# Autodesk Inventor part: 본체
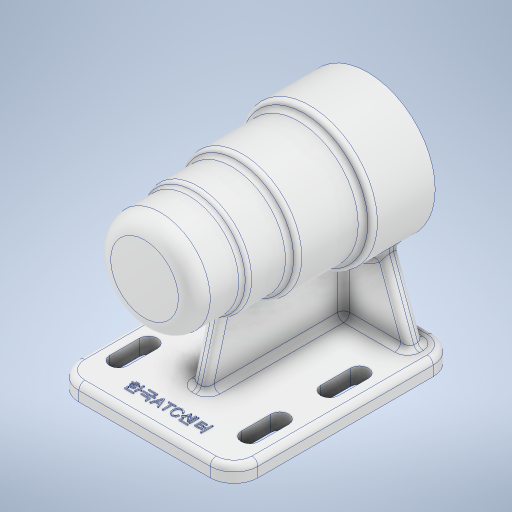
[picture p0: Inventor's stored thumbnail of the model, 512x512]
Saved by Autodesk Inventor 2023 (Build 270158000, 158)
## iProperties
Created: 2022-07
Part Number: 본체
Material: 알루미늄 6061
Document SubType Name: Modeling
Designer: owner
Density: 2.7 g/cm^3
Appearance: 알루미늄 - 평지
Mass: 691.322 g
Surface Area: 698.567 cm^2
Volume: 256.045 cm^3
Author: owner
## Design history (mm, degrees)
sketch "스케치1"
  geometry: L1 (-33, -56)-(33, -56); L2 (45, -44)-(45, 44); L3 (33, 56)-(-33, 56); L4 (-45, 44)-(-45, -44); L5 (-45, -56)-(45, 56); L6 (45, -56)-(-45, 56); A1 r 12 centre (33, 44) between (45, 44) and (33, 56); A2 r 12 centre (-33, 44) between (-33, 56) and (-45, 44); A3 r 12 centre (-33, -44) between (-45, -44) and (-33, -56); A4 r 12 centre (33, -44) between (33, -56) and (45, -44); 1 further point
  constraints: 12 end point, 8 point on circle, 8 point on line, 8 tangent, 4 centre point, 3 equal radius, 2 midpoint, 2 parallel, 1 horizontal, 1 perpendicular
  dimensions: "d0" = 90 distance of L6.end L5.end; "d1" = 112 distance of L5.end L6.start; "d2" = 12 radius of A1
extrude "돌출1" new body sketch "스케치1" distance "d3" = 8; taper "d4" = 0 deg
sketch "스케치2"
  geometry: L1 (70, 56)-(70, -56); L2 (0, 44)-(0, -44) reference; L3 (95, 48)-(95, 32); L4 (95, 32)-(97, 32); L5 (97, 32)-(97, 10); L6 (97, 10)-(100, 10); L7 (100, 10)-(100, -24); L8 (100, -24)-(104, -24); L9 (104, -24)-(104, -56); L10 (104, -56)-(92, -56); L11 (87, 56)-(70, 56); L12 (70, 50)-(77.5, 50); L13 (80.5, 47)-(80.5, 47); L14 (80.5, 47)-(85.7, 47); L15 (86, 46.7)-(86, 43); L16 (86, 43)-(87.2, 43); L17 (87.5, 42.7)-(87.5, 25); L18 (87.5, 25)-(90.7, 25); L19 (91, 24.7)-(91, 13); L20 (91, 13)-(91, 13); L21 (94, 10)-(94, -38); L22 (91, -41)-(91, -41); L23 (91, -41)-(91, -55); L24 (91, -55)-(92, -56); A1 r 8 centre (87, 48) between (95, 48) and (87, 56); A2 r 0.3 centre (85.7, 46.7) between (86, 46.7) and (85.7, 47); A3 r 0.3 centre (87.2, 42.7) between (87.5, 42.7) and (87.2, 43); A4 r 0.3 centre (90.7, 24.7) between (91, 24.7) and (90.7, 25); A5 r 3 centre (77.5, 47) between (80.5, 47) and (77.5, 50); A6 r 3 centre (91, 10) between (94, 10) and (91, 13); A7 r 3 centre (91, -38) between (91, -41) and (94, -38); 8 further points
  constraints: 46 end point, 18 perpendicular, 14 point on circle, 14 tangent, 7 centre point, 6 point on line, 4 equal radius, 2 horizontal, 2 midpoint, 1 horizontal alignment, 1 vertical
  dimensions: "d5" = 70 distance between parallel lines of L2 L1; "d6" = 112 distance of L1.start L1.end; "d7" = 24 distance between parallel lines of L4 L11; "d8" = 46 distance between parallel lines of L6 L11; "d9" = 80 distance between parallel lines of L8 L11; "d10" = 68 diameter of L9 L1; "d11" = 60 diameter of L7 L1; "d12" = 54 diameter of L5 L1; "d13" = 50 diameter of L3 L1; "d14" = 8 radius of A1; "d15" = 21 diameter of L13 L1; "d16" = 32 diameter of L15 L1; "d17" = 35 diameter of L17 L1; "d18" = 3 distance between parallel lines of L14 L12; "d19" = 4 distance between parallel lines of L16 L14; "d20" = 18 distance between parallel lines of L18 L16; "d21" = 12 distance between parallel lines of L20 L18; "d22" = 54 distance between parallel lines of L22 L20; "d23" = 15 distance between parallel lines of L10 L22; "d24" = 48 diameter of L21 L1; "d25" = 42 diameter of L23 L1; "d26" = 42 diameter of L19 L1; "d27" = 0.3 radius of A2; "d28" = 3 radius of A5; "d29" = 1 distance of L23.end point (91, -56); "d30" = 1 distance of L10.end point (91, -56) (= d29)
revolve "회전1" sketch "스케치2" stored, may be unused: angle "d31" = 90 deg
sketch "스케치3"
  geometry: L1 (-33, -21)-(-33, -36); L2 (-37.5, -21)-(-37.5, -36); L3 (-28.5, -36)-(-28.5, -21); L4 (-33, -56)-(33, -56) reference; L5 (-33, 19)-(-33, 4); L6 (-37.5, 19)-(-37.5, 4); L7 (-28.5, 4)-(-28.5, 19); A1 r 4.5 centre (-33, -21) between (-28.5, -21) and (-37.5, -21); A2 r 4.5 centre (-33, -36) between (-37.5, -36) and (-28.5, -36); A3 r 4.5 centre (-33, 19) between (-28.5, 19) and (-37.5, 19); A4 r 4.5 centre (-33, 4) between (-37.5, 4) and (-28.5, 4); 3 further points
  constraints: 16 end point, 8 point on circle, 8 tangent, 4 centre point, 2 midpoint, 2 parallel, 2 vertical
  dimensions: "d32" = 9 diameter of A2; "d33" = 20 distance from line of L4 L1.end; "d34" = 15 distance of L1.start L1.end; "d35" = 33 horizontal distance of point (0, 0) point (-33, -28.5); "d36" = 9 diameter of A4; "d37" = 15 distance of L5.start L5.end; "d38" = 25 distance of L1.start L5.end; "d39" = 33 horizontal distance of point (0, 0) point (-33, 11.5)
extrude "돌출2" cut sketch "스케치3" extent not by distance; stored distance "d40" = 0; taper "d41" = 0 deg
sketch "스케치5"
  geometry: L1 (8, 44)-(8, -44) reference; L2 (43, 32)-(43, 10) reference; L3 (40, 10)-(40, -24) reference; L4 (36, -24)-(36, -56) reference; L5 (43, 19.622)-(8, 29); L6 (8, -44)-(8, 44) reference; L7 (36, -48)-(8, -48); L8 (0, -56)-(8, -56) reference; L9 (8, 29)-(8, -48); L10 (8, -56)-(8, -44) reference; 1 further point
  constraints: 6 end point, 4 point on line, 1 collinear, 1 perpendicular
  dimensions: "d42" = 105 deg angle of L1 L5; "d43" = 85 distance from line of L8 L5.end; "d44" = 8 distance from line of L8 L7.end
feature "리브1" sketch "스케치5" dims "d45" = 1, "d46" = 8, "d47" = 0, "d48" = 0, "d49" = 1, "d50" = 1
node "작업 평면1"
sketch "스케치6"
  geometry: L1 (23.409, 45.342)-(37, 8); L2 (-23.409, 45.342)-(-37, 8); L3 (45, 0)-(45, 8) reference; L4 (-45, 0)-(-45, 8) reference; L5 (45, 8)-(33, 8) reference; L6 (-33, 8)-(-45, 8) reference; L7 (37, 8)-(-37, 8); L8 (-33, 8)-(33, 8) reference; A1 r 34 centre (0, 70) between (23.409, 45.342) and (-23.409, 45.342) reference; 3 further points
  constraints: 6 end point, 2 midpoint, 2 point on circle, 1 coincident, 1 collinear
  dimensions: "d56" = 110 deg angle of L5 L1; "d57" = 110 deg angle of L2 L6; "d58" = 8 distance from line of L2.end L4; "d59" = 8 distance from line of L3 L1.end
extrude "돌출3" join sketch "스케치6" distance "d60" = 8; taper "d61" = 0 deg
fillet "모깎기1" dims "d62" = 3
fillet "모깎기2" dims "d63" = 3
fillet "모깎기3" dims "d64" = 3
fillet "모깎기4" dims "d65" = 3
fillet "모깎기6" dims "d67" = 3
fillet "모깎기7" dims "d68" = 3
fillet "모깎기8" dims "d69" = 3
sketch "스케치7" dims "d77" = 52
  geometry: A1 r 30 centre (0, 0) between (6.364, -29.317) and (-6.364, -29.317) reference; 3 further points
  constraints: 2 horizontal alignment, 1 coincident, 2 other
hole "구멍1" sketch "스케치7" at (-26, 0) diameter "d70" = 3.242; stored, may be unused: countersink angle "d74" = 90 deg, drill point angle "d76" = 118 deg; dims "d71" = 8, "d72" = 4, "d73" = 2, "d75" = 11
sketch "스케치8"
  geometry: L1 (-33, -56)-(33, -56) reference; A1 r 4.5 centre (-33, -36) between (-37.5, -36) and (-28.5, -36) reference; 2 further points
  constraints: 1 vertical alignment, 1 other
  dimensions: "d83" = 12 distance from line of L1 point (0, -44)
feature "엠보싱1" sketch "스케치8" dims "d84" = 0.5, "d85" = 0
node "솔리드1"
mirror "미러1"
pattern_circular "원형 패턴1" dims angle "d79" = 360 deg
feature "A9D066F2-1C7D-4E18-AEED-F7BC21143FA4" dims "d70" = 3.242, "d71" = 8, "d72" = 4, "d73" = 2, "d74" = 90 deg, "d75" = 11, "d76" = 118 deg
other parameters: "d51" = -48
